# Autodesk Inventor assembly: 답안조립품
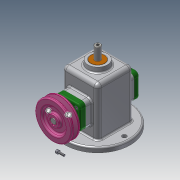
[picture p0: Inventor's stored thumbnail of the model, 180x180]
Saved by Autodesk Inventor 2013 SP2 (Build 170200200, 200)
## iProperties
Created: 2021-08
Part Number: 답안조립품
Document SubType Name: Assembly
Designer: kum60
Author: kum60
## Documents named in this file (16)
- C:\Users\kum60\Desktop\710806V1018\710806V1018 (2)\답안조립품.iam
- C:\Users\kum60\Desktop\710806V1018\710806V1018 (2)\본체.ipt
- C:\Users\kum60\Desktop\710806V1018\710806V1018 (2)\V벨트풀리.ipt
- C:\Users\kum60\Desktop\710806V1018\710806V1018 (2)\고정핀 1.2x8.ipt
- C:\Users\kum60\Desktop\710806V1018\710806V1018 (2)\뒤커버.ipt
- C:\Users\kum60\Desktop\710806V1018\710806V1018 (2)\링크.ipt
- C:\Users\kum60\Desktop\710806V1018\710806V1018 (2)\멈춤나사 M3x8.ipt
- C:\Users\kum60\Desktop\710806V1018\710806V1018 (2)\베어링 12x32x10.ipt
- C:\Users\kum60\Desktop\710806V1018\710806V1018 (2)\볼트 M4.ipt
- C:\Users\kum60\Desktop\710806V1018\710806V1018 (2)\부시.ipt
- C:\Users\kum60\Desktop\710806V1018\710806V1018 (2)\슬라이드.ipt
- C:\Users\kum60\Desktop\710806V1018\710806V1018 (2)\앞커버.ipt
- C:\Users\kum60\Desktop\710806V1018\710806V1018 (2)\오일 실 12 25 7.ipt
- C:\Users\kum60\Desktop\710806V1018\710806V1018 (2)\키 4x4x10.ipt
- C:\Users\kum60\Desktop\710806V1018\710806V1018 (2)\편심축.ipt
- C:\Users\kum60\Desktop\710806V1018\710806V1018 (2)\핀 5x18.ipt
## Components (3 placed, 3 different names)
1. V벨트풀리:1
2. 고정핀 1.2x8:1
3. 핀 5x18:1
